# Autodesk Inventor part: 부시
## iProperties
Company: 한국ATC센터
Created: 2014-01
Part Number: 부시
Document SubType Name: Modeling
Designer: KYOUNG IL JANG
Density: 1 g/cm^3
Material: 기본값
Mass: 8.58964 g
Surface Area: 43.3569 cm^2
Volume: 8.58964 cm^3
Vendor: CBT Solutions
Author: KYOUNG IL JANG
